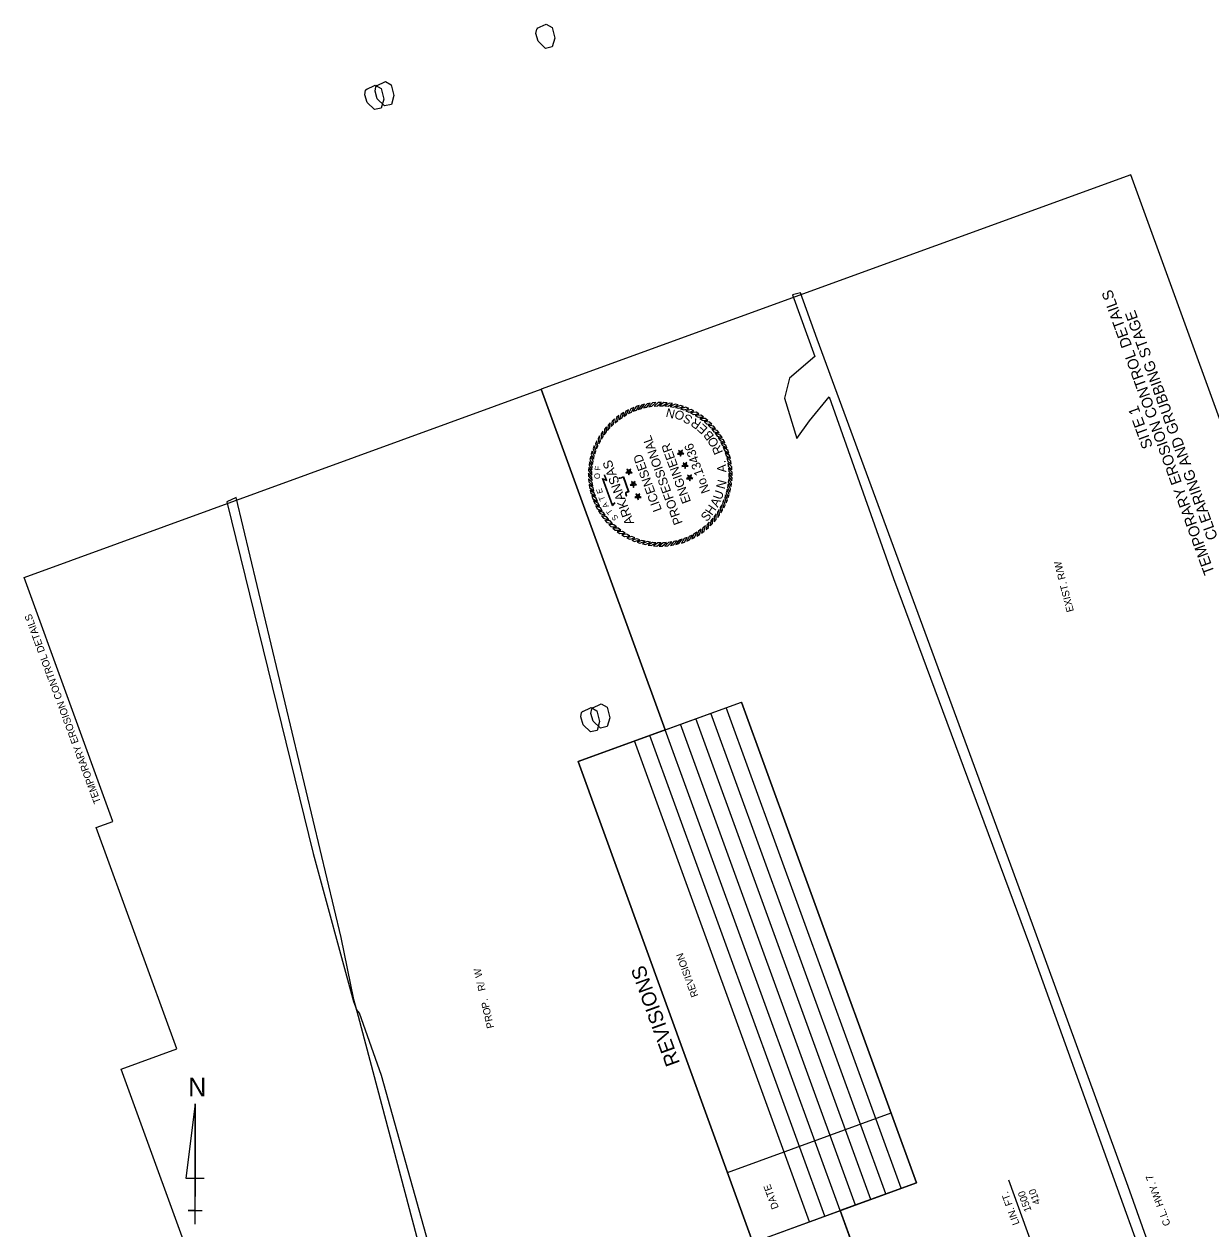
# Model space of a CAD drawing. Extents: x 986289 to 987754, y 1871116 to 1873096.
# Drawn here: x 986289 to 987265, y 1872096 to 1873096 of the extents above; entities that cross this region are included whole.
import ezdxf

# ---------------------------------------------------------------- set-up
doc = ezdxf.new("R2010")
doc.units = 0
for name, color, linetype in [('1', 7, 'Continuous'), ('44', 7, 'Continuous'), ('60', 7, 'Continuous'), ('63', 7, 'Continuous'), ('Default', 7, 'Continuous'), ('G-ANNO-SYMB', 7, 'Continuous'), ('NO PLOT', 7, 'Continuous'), ('R_Draft', 7, 'Continuous'), ('S_TREE', 7, 'Continuous')]:
    doc.layers.add(name, color=color, linetype=linetype)

msp = doc.modelspace()

# ---------------------------------------------------------------- linework, layer by layer
at = {"layer": '1'}
for p, q in [((986821.2, 1872510.2), (986718.3, 1872793)), ((987064.5, 1871841.9), (986966.6, 1872110.8))]:
    msp.add_line(p, q, dxfattribs=at)
at = {"layer": '44'}
msp.add_line((987186.2, 1871917.4), (987106.6, 1872136.2), dxfattribs=at)
at = {"layer": '63'}
for p, q in [((986430.7, 1872199.4), (986423, 1872137.8)), ((986430.7, 1872099.4), (986430.7, 1872199.4)), ((986430.7, 1872199.4), (986430.7, 1872122.5)), ((986423, 1872137.8), (986438.4, 1872137.8)), ((986430.7, 1872099.4), (986430.7, 1872122.5)), ((986430.7, 1872110.9), (986424.9, 1872110.9)), ((986424.9, 1872110.9), (986436.5, 1872110.9)), ((986430.7, 1872099.4), (986430.7, 1872110.9))]:
    msp.add_line(p, q, dxfattribs=at)
at = {"layer": 'Default'}
for p, q in [((986748.9, 1872483.8), (986884.7, 1872533.2)), ((987017.3, 1872129.3), (986872, 1872528.6)), ((987030, 1872133.9), (986884.7, 1872533.2)), ((986979.3, 1872115.4), (986833.9, 1872514.8)), ((986979.3, 1872115.4), (986833.9, 1872514.8)), ((986992, 1872120), (986846.6, 1872519.4)), ((987004.6, 1872124.6), (986859.3, 1872524)), ((986953.9, 1872106.2), (986808.5, 1872505.5)), ((986966.6, 1872110.8), (986821.2, 1872510.2)), ((986941.2, 1872101.5), (986795.9, 1872500.9)), ((986894.2, 1872084.4), (986748.9, 1872483.8)), ((986873.1, 1872142.5), (987008.9, 1872192)), ((986894.2, 1872084.4), (987030, 1872133.9))]:
    msp.add_line(p, q, dxfattribs=at)
at = {"layer": 'G-ANNO-SYMB'}
for points in [[(986790.9, 1872775.9), (986788.6, 1872774.7), (986786.8, 1872770.5), (986789.2, 1872771.9)], [(986795.2, 1872777.8), (986792.8, 1872776.8), (986790.7, 1872772.8), (986793.2, 1872774)], [(986799.6, 1872779.4), (986797.2, 1872778.6), (986794.7, 1872774.7), (986797.3, 1872775.7)], [(986804.1, 1872780.6), (986801.6, 1872779.9), (986798.9, 1872776.3), (986801.6, 1872777.1)], [(986808.7, 1872781.4), (986806.2, 1872781), (986803.2, 1872777.5), (986805.9, 1872778.2)], [(986813.4, 1872781.9), (986810.8, 1872781.7), (986807.6, 1872778.5), (986810.3, 1872778.9)], [(986818.1, 1872782), (986815.5, 1872782), (986812, 1872779), (986814.8, 1872779.2)], [(986822.8, 1872781.7), (986820.2, 1872781.9), (986816.5, 1872779.3), (986819.2, 1872779.2)], [(986827.4, 1872781.1), (986824.9, 1872781.5), (986820.9, 1872779.2), (986823.7, 1872778.9)], [(986832, 1872780.1), (986829.5, 1872780.7), (986825.4, 1872778.7), (986828.1, 1872778.2)], [(986836.5, 1872778.8), (986834, 1872779.6), (986829.8, 1872777.9), (986832.5, 1872777.2)], [(986840.8, 1872777.1), (986838.5, 1872778.1), (986834.1, 1872776.7), (986836.7, 1872775.8)], [(986845.1, 1872775.1), (986842.8, 1872776.2), (986838.3, 1872775.2), (986840.9, 1872774.1)], [(986775.6, 1872765.2), (986773.8, 1872763.3), (986773.4, 1872758.8), (986775.3, 1872760.9)], [(986779.1, 1872768.3), (986777.2, 1872766.6), (986776.4, 1872762.1), (986778.4, 1872764)], [(986782.8, 1872771.1), (986780.8, 1872769.6), (986779.7, 1872765.2), (986781.8, 1872767)], [(986786.8, 1872773.7), (986784.6, 1872772.3), (986783.1, 1872768), (986785.4, 1872769.6)], [(986849.1, 1872772.7), (986846.9, 1872774.1), (986842.4, 1872773.4), (986844.9, 1872772.1)], [(986853, 1872770.1), (986850.9, 1872771.6), (986846.3, 1872771.3), (986848.7, 1872769.8)], [(986856.6, 1872767.1), (986854.6, 1872768.8), (986850.1, 1872768.8), (986852.3, 1872767.2)], [(986860, 1872763.9), (986858.2, 1872765.7), (986853.6, 1872766.1), (986855.7, 1872764.3)], [(986769.4, 1872758.1), (986768, 1872756.1), (986768.3, 1872751.5), (986769.7, 1872753.8)], [(986772.4, 1872761.8), (986770.8, 1872759.8), (986770.7, 1872755.2), (986772.4, 1872757.5)], [(986863.1, 1872760.4), (986861.4, 1872762.3), (986856.9, 1872763.1), (986858.9, 1872761.1)], [(986866, 1872756.7), (986864.4, 1872758.8), (986860, 1872759.9), (986861.8, 1872757.7)], [(986868.5, 1872752.8), (986867.2, 1872754.9), (986862.8, 1872756.4), (986864.4, 1872754.1)], [(986762.4, 1872746), (986761.4, 1872743.6), (986762.8, 1872739.3), (986763.7, 1872741.9)], [(986764.4, 1872750.2), (986763.3, 1872747.9), (986764.3, 1872743.5), (986765.4, 1872746)], [(986766.8, 1872754.3), (986765.5, 1872752.1), (986766.1, 1872747.6), (986767.4, 1872750)], [(986870.7, 1872748.6), (986869.6, 1872750.9), (986865.4, 1872752.7), (986866.8, 1872750.3)], [(986872.6, 1872744.3), (986871.6, 1872746.7), (986867.6, 1872748.8), (986868.8, 1872746.3)], [(986874.2, 1872739.9), (986873.4, 1872742.4), (986869.5, 1872744.8), (986870.5, 1872742.2)], [(986759.4, 1872737.1), (986758.8, 1872734.6), (986760.8, 1872730.6), (986761.3, 1872733.3)], [(986760.7, 1872741.6), (986759.9, 1872739.2), (986761.7, 1872735), (986762.3, 1872737.6)], [(986834.1, 1872740.1), (986833.1, 1872740.4), (986831.5, 1872739.2), (986833.5, 1872739.2)], [(986834.1, 1872740.1), (986834, 1872741.1), (986832.4, 1872742.2), (986833.1, 1872740.4)], [(986834.1, 1872740.1), (986833.5, 1872739.2), (986834.1, 1872737.4), (986834.7, 1872739.3)], [(986834.1, 1872740.1), (986835, 1872740.5), (986835.6, 1872742.4), (986834, 1872741.1)], [(986834.1, 1872740.1), (986834.7, 1872739.3), (986836.7, 1872739.3), (986835, 1872740.5)], [(986875.4, 1872735.4), (986874.8, 1872737.9), (986871.1, 1872740.6), (986871.9, 1872738)], [(986876.2, 1872730.8), (986875.8, 1872733.3), (986872.4, 1872736.3), (986873, 1872733.6)], [(986757.8, 1872727.9), (986757.6, 1872725.4), (986760.3, 1872721.6), (986760.3, 1872724.4)], [(986758.4, 1872732.6), (986758, 1872730), (986760.4, 1872726.1), (986760.6, 1872728.9)], [(986791.1, 1872724.5), (986790.1, 1872724.8), (986788.6, 1872723.5), (986790.5, 1872723.6)], [(986791.1, 1872724.5), (986791.1, 1872725.5), (986789.4, 1872726.6), (986790.1, 1872724.8)], [(986791.1, 1872724.5), (986790.5, 1872723.6), (986791.2, 1872721.8), (986791.8, 1872723.7)], [(986791.1, 1872724.5), (986792.1, 1872724.8), (986792.7, 1872726.7), (986791.1, 1872725.5)], [(986791.1, 1872724.5), (986791.8, 1872723.7), (986793.7, 1872723.7), (986792.1, 1872724.8)], [(986837.8, 1872729.8), (986836.8, 1872730.1), (986835.2, 1872728.9), (986837.2, 1872729)], [(986837.8, 1872729.8), (986837.7, 1872730.9), (986836.1, 1872732), (986836.8, 1872730.1)], [(986837.8, 1872729.8), (986837.2, 1872729), (986837.9, 1872727.1), (986838.4, 1872729)], [(986837.8, 1872729.8), (986838.8, 1872730.2), (986839.3, 1872732.1), (986837.7, 1872730.9)], [(986837.8, 1872729.8), (986838.4, 1872729), (986840.4, 1872729.1), (986838.8, 1872730.2)], [(986876.7, 1872726.1), (986876.5, 1872728.7), (986873.3, 1872732), (986873.7, 1872729.2)], [(986876.8, 1872721.5), (986876.8, 1872724), (986873.9, 1872727.5), (986874.1, 1872724.8)], [(986757.5, 1872723.2), (986757.5, 1872720.7), (986760.5, 1872717.2), (986760.3, 1872719.9)], [(986757.6, 1872718.6), (986757.9, 1872716), (986761.1, 1872712.7), (986760.7, 1872715.5)], [(986794.9, 1872714.2), (986793.9, 1872714.5), (986792.3, 1872713.3), (986794.3, 1872713.4)], [(986794.9, 1872714.2), (986794.8, 1872715.3), (986793.2, 1872716.4), (986793.9, 1872714.5)], [(986794.9, 1872714.2), (986795.8, 1872714.6), (986796.4, 1872716.5), (986794.8, 1872715.3)], [(986794.9, 1872714.2), (986795.5, 1872713.4), (986797.5, 1872713.5), (986795.8, 1872714.6)], [(986841.5, 1872719.6), (986840.5, 1872719.9), (986839, 1872718.7), (986840.9, 1872718.7)], [(986841.5, 1872719.6), (986841.5, 1872720.6), (986839.8, 1872721.7), (986840.5, 1872719.9)], [(986841.5, 1872719.6), (986840.9, 1872718.7), (986841.6, 1872716.9), (986842.2, 1872718.8)], [(986841.5, 1872719.6), (986842.5, 1872720), (986843, 1872721.9), (986841.5, 1872720.6)], [(986841.5, 1872719.6), (986842.2, 1872718.8), (986844.1, 1872718.8), (986842.5, 1872720)], [(986876, 1872712.1), (986876.3, 1872714.7), (986874, 1872718.6), (986873.7, 1872715.8)], [(986876.6, 1872716.8), (986876.8, 1872719.3), (986874.1, 1872723.1), (986874.1, 1872720.3)], [(986758.1, 1872713.9), (986758.5, 1872711.4), (986762, 1872708.4), (986761.4, 1872711.1)], [(986759, 1872709.3), (986759.6, 1872706.8), (986763.3, 1872704.1), (986762.4, 1872706.7)], [(986760.2, 1872704.8), (986761, 1872702.3), (986764.9, 1872699.9), (986763.8, 1872702.5)], [(986794.9, 1872714.2), (986794.3, 1872713.4), (986795, 1872711.5), (986795.5, 1872713.4)], [(986798.6, 1872704), (986798.6, 1872705), (986796.9, 1872706.1), (986797.6, 1872704.3)], [(986798.6, 1872704), (986799.6, 1872704.3), (986800.1, 1872706.2), (986798.6, 1872705)], [(986798.6, 1872704), (986799.2, 1872703.2), (986801.2, 1872703.2), (986799.6, 1872704.3)], [(986871.9, 1872698.7), (986872.9, 1872701.1), (986871.5, 1872705.4), (986870.7, 1872702.8)], [(986873.6, 1872703.1), (986874.4, 1872705.5), (986872.7, 1872709.7), (986872, 1872707.1)], [(986875, 1872707.6), (986875.6, 1872710), (986873.5, 1872714.1), (986873.1, 1872711.4)], [(986761.7, 1872700.4), (986762.7, 1872698), (986766.8, 1872695.9), (986765.6, 1872698.4)], [(986763.6, 1872696.1), (986764.8, 1872693.8), (986769, 1872692), (986767.6, 1872694.4)], [(986798.6, 1872704), (986797.6, 1872704.3), (986796, 1872703), (986798, 1872703.1)], [(986798.6, 1872704), (986798, 1872703.1), (986798.7, 1872701.2), (986799.2, 1872703.2)], [(986867.6, 1872690.4), (986868.9, 1872692.6), (986868.2, 1872697.1), (986866.9, 1872694.7)], [(986869.9, 1872694.5), (986871.1, 1872696.8), (986870, 1872701.2), (986869, 1872698.7)], [(986765.8, 1872691.9), (986767.2, 1872689.8), (986771.5, 1872688.3), (986769.9, 1872690.6)], [(986768.4, 1872688), (986769.9, 1872685.9), (986774.4, 1872684.8), (986772.6, 1872687)], [(986771.2, 1872684.3), (986772.9, 1872682.4), (986777.4, 1872681.6), (986775.5, 1872683.6)], [(986858.7, 1872679.5), (986860.5, 1872681.4), (986860.9, 1872685.9), (986859.1, 1872683.8)], [(986862, 1872682.9), (986863.6, 1872684.9), (986863.7, 1872689.5), (986862, 1872687.2)], [(986864.9, 1872686.6), (986866.4, 1872688.6), (986866.1, 1872693.2), (986864.6, 1872690.9)], [(986774.4, 1872680.8), (986776.2, 1872679), (986780.7, 1872678.6), (986778.7, 1872680.4)], [(986777.8, 1872677.6), (986779.7, 1872675.9), (986784.3, 1872675.9), (986782.1, 1872677.5)], [(986781.4, 1872674.6), (986783.5, 1872673.1), (986788, 1872673.4), (986785.7, 1872674.9)], [(986847.6, 1872671), (986849.8, 1872672.4), (986851.2, 1872676.7), (986849, 1872675.1)], [(986851.5, 1872673.6), (986853.6, 1872675.1), (986854.7, 1872679.5), (986852.6, 1872677.7)], [(986855.2, 1872676.4), (986857.2, 1872678.1), (986857.9, 1872682.6), (986856, 1872680.7)], [(986785.2, 1872672), (986787.4, 1872670.6), (986792, 1872671.3), (986789.5, 1872672.6)], [(986789.3, 1872669.6), (986791.6, 1872668.5), (986796, 1872669.5), (986793.5, 1872670.6)], [(986793.5, 1872667.6), (986795.9, 1872666.6), (986800.3, 1872668), (986797.6, 1872668.9)], [(986797.9, 1872665.9), (986800.3, 1872665.1), (986804.6, 1872666.8), (986801.9, 1872667.5)], [(986802.4, 1872664.6), (986804.9, 1872664), (986809, 1872666), (986806.2, 1872666.5)], [(986807, 1872663.6), (986809.5, 1872663.2), (986813.4, 1872665.5), (986810.7, 1872665.8)], [(986811.6, 1872663), (986814.2, 1872662.8), (986817.9, 1872665.4), (986815.1, 1872665.5)], [(986816.3, 1872662.7), (986818.8, 1872662.7), (986822.4, 1872665.7), (986819.6, 1872665.5)], [(986821, 1872662.8), (986823.5, 1872663), (986826.8, 1872666.2), (986824, 1872665.8)], [(986825.6, 1872663.3), (986828.2, 1872663.7), (986831.2, 1872667.2), (986828.5, 1872666.5)], [(986830.2, 1872664.1), (986832.7, 1872664.8), (986835.4, 1872668.4), (986832.8, 1872667.6)], [(986834.8, 1872665.3), (986837.2, 1872666.1), (986839.6, 1872670), (986837, 1872669)], [(986839.2, 1872666.9), (986841.5, 1872667.9), (986843.7, 1872671.9), (986841.2, 1872670.7)], [(986843.5, 1872668.8), (986845.7, 1872670), (986847.5, 1872674.2), (986845.1, 1872672.8)]]:
    msp.add_lwpolyline(points, close=True, dxfattribs=at)
for points in [[(986779.8, 1872698.6), (986777.4, 1872696.2), (986769.2, 1872718.8), (986772.2, 1872717.8), (986771.6, 1872719.3), (986771.2, 1872720.6), (986770.8, 1872721.9)], [(986779.5, 1872698.8), (986777.6, 1872696.9), (986769.8, 1872718.2), (986772.9, 1872717.2), (986772, 1872719.5), (986771.5, 1872720.7), (986771.2, 1872722)], [(986782.6, 1872719.4), (986783.1, 1872719.1), (986783.8, 1872719.1), (986785.1, 1872719.5), (986786.3, 1872719.9), (986790.6, 1872708), (986788.9, 1872707.4), (986788.2, 1872707.1), (986788.2, 1872706.2), (986788.8, 1872704.5), (986788.6, 1872704.2)], [(986782.8, 1872719.8), (986783.2, 1872719.5), (986783.7, 1872719.5), (986785, 1872719.8), (986786.5, 1872720.4), (986791.1, 1872707.8), (986789, 1872707), (986788.5, 1872706.8), (986788.6, 1872706.3), (986789.2, 1872704.5), (986788.9, 1872704)]]:
    msp.add_lwpolyline(points, dxfattribs=at)
at = {"layer": 'NO PLOT'}
for points in [[(987753.7, 1871472.1), (987208, 1872971.2), (986718.3, 1872793), (986821.2, 1872510.2), (986884.7, 1872533.2), (987030, 1872133.9), (986966.6, 1872110.8), (987064.5, 1871841.9), (987122.5, 1871863), (987239.7, 1871541), (987181.7, 1871519.9), (987263.9, 1871293.8)], [(987753.7, 1871472.1), (987208, 1872971.2), (986718.3, 1872793), (986821.2, 1872510.2), (986884.7, 1872533.2), (987030, 1872133.9), (986966.6, 1872110.8), (987064.5, 1871841.9), (987122.5, 1871863), (987239.7, 1871541), (987181.7, 1871519.9), (987263.9, 1871293.8)], [(987753.7, 1871472.1), (987208, 1872971.2), (986718.3, 1872793), (986821.2, 1872510.2), (986884.7, 1872533.2), (987030, 1872133.9), (986966.6, 1872110.8), (987064.5, 1871841.9), (987122.5, 1871863), (987239.7, 1871541), (987181.7, 1871519.9), (987263.9, 1871293.8)], [(987491.8, 1871372.7), (987456.2, 1871457.1), (987369.2, 1871671.9), (987295.1, 1871880), (987205.8, 1872130.8), (987121, 1872363), (986947.4, 1872834.5), (986933.7, 1872873.1), (986927.1, 1872871.4), (986945.7, 1872820.2), (986924.6, 1872802.1), (986920.3, 1872785.6), (986930.5, 1872752.2), (986941.1, 1872766.8), (986957.6, 1872786.8), (987010.9, 1872635.9), (987123.9, 1872331.6), (987288.2, 1871875.9), (987395.4, 1871570.4), (987485.3, 1871371)], [(986774.2, 1871115.6), (986369.2, 1872228.3), (986415.6, 1872245.1), (986348.7, 1872429.1), (986362.4, 1872434.1), (986288.7, 1872636.6), (986718.3, 1872793), (986821.2, 1872510.2), (986748.9, 1872483.8), (986894.2, 1872084.4), (986966.6, 1872110.8), (987064.5, 1871841.9), (987008.8, 1871821.6), (987125.9, 1871499.6), (987181.7, 1871519.9), (987263.9, 1871293.8)], [(986774.2, 1871115.6), (986369.2, 1872228.3), (986415.6, 1872245.1), (986348.7, 1872429.1), (986362.4, 1872434.1), (986288.7, 1872636.6), (986718.3, 1872793), (986821.2, 1872510.2), (986748.9, 1872483.8), (986894.2, 1872084.4), (986966.6, 1872110.8), (987064.5, 1871841.9), (987008.8, 1871821.6), (987125.9, 1871499.6), (987181.7, 1871519.9), (987263.9, 1871293.8)], [(986774.2, 1871115.6), (986369.2, 1872228.3), (986415.6, 1872245.1), (986348.7, 1872429.1), (986362.4, 1872434.1), (986288.7, 1872636.6), (986718.3, 1872793), (986821.2, 1872510.2), (986748.9, 1872483.8), (986894.2, 1872084.4), (986966.6, 1872110.8), (987064.5, 1871841.9), (987008.8, 1871821.6), (987125.9, 1871499.6), (987181.7, 1871519.9), (987263.9, 1871293.8)]]:
    msp.add_lwpolyline(points, close=True, dxfattribs=at)
msp.add_lwpolyline([(986631.8, 1872057.7), (986585.5, 1872222.9), (986567.3, 1872274.8), (986564.8, 1872277.8), (986564.8, 1872277.9), (986564.7, 1872278.2), (986562.6, 1872286.2), (986552, 1872337.5), (986464.8, 1872703.1), (986457, 1872699.6), (986528.8, 1872407.3), (986562.4, 1872284.6), (986564.8, 1872277.8), (986564.8, 1872277.8), (986564.9, 1872277.4), (986566.3, 1872272.3), (986630.5, 1872029.9)], dxfattribs=at)
at = {"layer": 'S_TREE'}
for points in [[(986715, 1873092.8), (986722.5, 1873096.3), (986727.3, 1873093.6), (986729.5, 1873084.7), (986727.5, 1873077.4), (986721.8, 1873076.1), (986715.7, 1873082), (986713.9, 1873088.4), (986714.5, 1873092.1), (986715.7, 1873093.3)], [(986572.9, 1873042), (986580.4, 1873045.5), (986585.2, 1873042.8), (986587.4, 1873033.9), (986585.4, 1873026.6), (986579.7, 1873025.3), (986573.6, 1873031.2), (986571.8, 1873037.6), (986572.4, 1873041.3), (986573.6, 1873042.5)], [(986581.4, 1873045.1), (986588.8, 1873048.6), (986593.7, 1873045.8), (986595.8, 1873037), (986593.9, 1873029.6), (986588.2, 1873028.4), (986582.1, 1873034.2), (986580.2, 1873040.7), (986580.9, 1873044.3), (986582, 1873045.6)], [(986752.2, 1872525.2), (986759.7, 1872528.6), (986764.5, 1872525.9), (986766.7, 1872517.1), (986764.8, 1872509.7), (986759.1, 1872508.4), (986753, 1872514.3), (986751.1, 1872520.8), (986751.7, 1872524.4), (986752.9, 1872525.6)], [(986760.7, 1872528.2), (986768.2, 1872531.7), (986773, 1872529), (986775.2, 1872520.2), (986773.2, 1872512.8), (986767.5, 1872511.5), (986761.4, 1872517.4), (986759.6, 1872523.8), (986760.2, 1872527.5), (986761.4, 1872528.7)]]:
    msp.add_lwpolyline(points, dxfattribs=at)

# ---------------------------------------------------------------- texts
at = {"layer": '1'}
msp.add_text('TEMPORARY EROSION CONTROL DETAILS', height=6, rotation=110.3231, dxfattribs=at).set_placement((986352.6, 1872450.1))
at = {"layer": '44'}
for s, p in [('LIN. FT.', (987115.7, 1872100)), ('1500', (987125.7, 1872111)), ('410', (987133.1, 1872116.9))]:
    msp.add_text(s, height=6, rotation=110, dxfattribs=at).set_placement(p)
at = {"layer": '60'}
for s, p in [('TEMPORARY EROSION CONTROL DETAILS', (987277.8, 1872640.8)), ('CLEARING AND GRUBBING STAGE', (987280.5, 1872669.6)), ('SITE 1', (987226.5, 1872745.5))]:
    msp.add_text(s, height=9, rotation=110, dxfattribs=at).set_placement(p)
at = {"layer": '63'}
msp.add_text('N', height=15.4, rotation=360, dxfattribs=at).set_placement((986425.1, 1872205.8))
at = {"layer": 'Default'}
for s, height, p in [('REVISION', 6, (986848.9, 1872289.3)), ('REVISIONS', 12, (986833.7, 1872233.3)), ('DATE', 6, (986915.7, 1872113.2))]:
    msp.add_text(s, height=height, rotation=110, dxfattribs=at).set_placement(p)
at = {"layer": 'G-ANNO-SYMB'}
for s, height, rotation, p in [('N', 7.5, 166.1007, (986830.1, 1872775.7)), ('O', 7.5, 154.7757, (986838.3, 1872773.2)), ('S', 7.5, 153.4878, (986844.7, 1872770)), ('R', 7.5, 145.6597, (986851.8, 1872765.3)), ('E', 7.5, 137.8315, (986857.1, 1872760.5)), ('PROFESSIONAL', 7.5, 110, (986835.9, 1872682)), ('B', 7.5, 128.885, (986862.3, 1872754.3)), ('ENGINEER', 7.5, 110, (986842.8, 1872699.7)), ('No.13436', 7.47, 110, (986858.7, 1872708.1)), ('O', 7.5, 121.4296, (986866.3, 1872747.7)), ('R', 7.5, 113.2287, (986869.4, 1872740.7)), ('LICENSED', 7.5, 110, (986818.6, 1872692.8)), ('F', 4.75, 85.3628, (986767.4, 1872725.3)), ('ARKANSAS', 7.75, 110, (986795.6, 1872681.9)), ('A', 7.5, 93.0991, (986872.1, 1872724.1)), ('.', 7.5, 101.3, (986871.7, 1872731.7)), ('O', 4.75, 91.2218, (986767.2, 1872718.5)), ('N', 7.5, 74.9326, (986870.6, 1872709.6)), ('E', 4.75, 106.672, (986769.6, 1872707.1)), ('U', 7.5, 70.9026, (986867.9, 1872700.6)), ('T', 4.75, 111.4789, (986771.6, 1872701.3)), ('A', 4.75, 118.6788, (986774.6, 1872695.9)), ('H', 7.5, 55.619, (986860.1, 1872687.7)), ('A', 7.5, 63.4472, (986864.9, 1872694.5)), ('T', 4.75, 126.9015, (986778, 1872691)), ('S', 4.75, 129.7726, (986782.6, 1872686.2)), ('S', 7.5, 48.1636, (986855.7, 1872682.5))]:
    msp.add_text(s, height=height, rotation=rotation, dxfattribs=at).set_placement(p)
at = {"layer": 'R_Draft'}
for s, rotation, p in [('EXIST. R/W', 104.4717, (987160.8, 1872608.8)), ('W', 102.8763, (986669.6, 1872305.1)), ('/', 102.8763, (986670.9, 1872299.4)), ('R', 102.8763, (986672.2, 1872293.9)), ('.', 102.8763, (986674.1, 1872285.2)), ('P', 102.8763, (986675.4, 1872279.6)), ('O', 102.8763, (986676.7, 1872273.9)), ('R', 102.8763, (986678, 1872268.4)), ('P', 102.8763, (986679.2, 1872262.9)), ('C.L. HWY. 7', 110.1045, (987241.2, 1872099.3))]:
    msp.add_text(s, height=6, rotation=rotation, dxfattribs=at).set_placement(p)

doc.saveas('drawing.dxf')
